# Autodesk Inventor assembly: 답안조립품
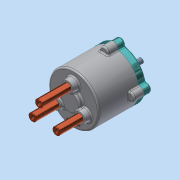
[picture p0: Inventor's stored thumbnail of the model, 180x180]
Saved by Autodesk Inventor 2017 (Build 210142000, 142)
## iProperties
Part Number: 답안조립품
Material: 일반
Document SubType Name: Assembly
Designer: MRC
Mass: 1236.64 g
Surface Area: 1770.13 cm^2
Volume: 433.789 cm^3
Density: 2.85078 g/cm^3
Author: MRC
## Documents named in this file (14)
- C:\Users\MRC\Desktop\610708V1007\답안조립품.iam
- C:\Users\MRC\Desktop\610708V1007\본체.ipt
- C:\Users\MRC\Desktop\610708V1007\가변스프링1.ipt
- C:\Users\MRC\Desktop\610708V1007\가변스프링2.ipt
- C:\Users\MRC\Desktop\610708V1007\가변스프링3.ipt
- C:\Users\MRC\Desktop\610708V1007\멈춤링 10 x 1.ipt
- C:\Users\MRC\Desktop\610708V1007\멈춤링 22 x 1.2.ipt
- C:\Users\MRC\Desktop\610708V1007\메인 축.ipt
- C:\Users\MRC\Desktop\610708V1007\베어링 NA 4900.ipt
- C:\Users\MRC\Desktop\610708V1007\볼트 M5.ipt
- C:\Users\MRC\Desktop\610708V1007\슬라이드 축.ipt
- C:\Users\MRC\Desktop\610708V1007\오일실.ipt
- C:\Users\MRC\Desktop\610708V1007\커버.ipt
- C:\Users\MRC\Desktop\610708V1007\판캠.ipt
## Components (3 placed, 3 different names)
1. 가변스프링1:1
2. 가변스프링2:1
3. 가변스프링3:1
